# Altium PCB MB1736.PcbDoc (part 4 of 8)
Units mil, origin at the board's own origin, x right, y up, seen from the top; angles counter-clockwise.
Board outline 5905.51 x 3779.53 mil, 6 copper layers (Top Layer, L2_GND, L3_SIG, L4_VCC, L5_GND, Bottom Layer), stack 117.811 mil thick; 481 components, 387 nets, 1904 pads, 1200 vias.
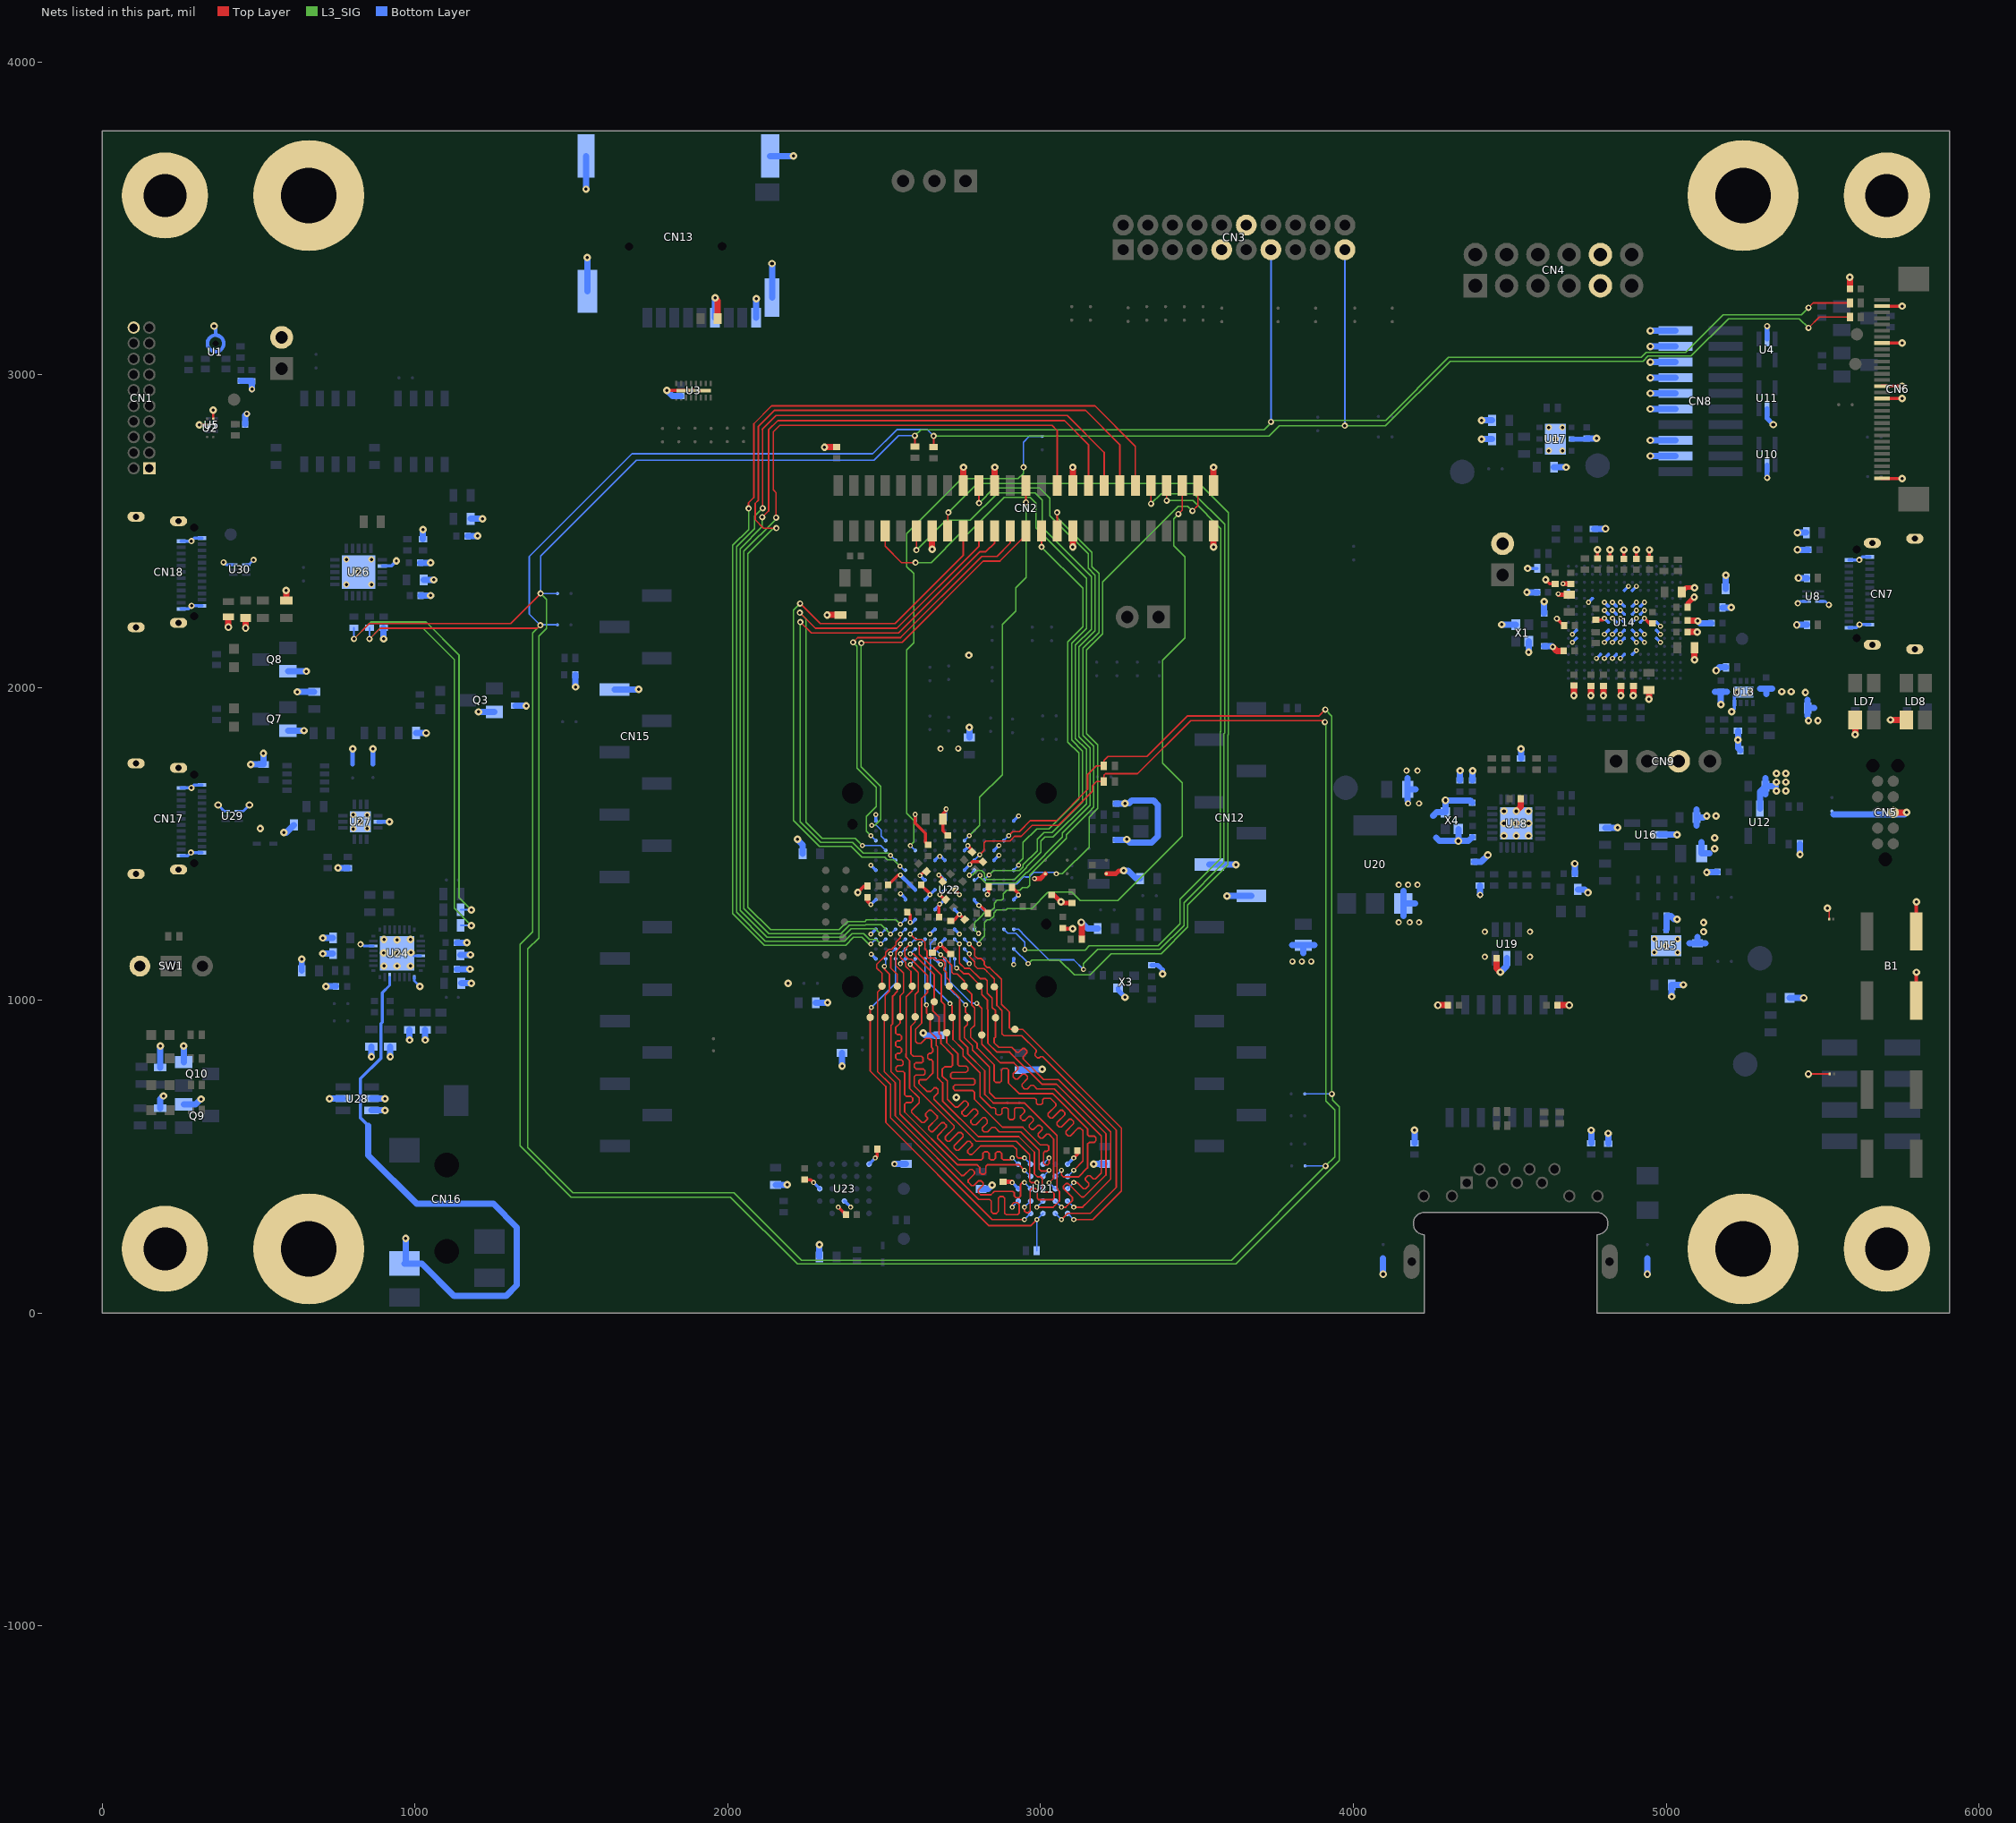
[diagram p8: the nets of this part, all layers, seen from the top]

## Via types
v1: diameter 20, hole 10, Top Layer to Bottom Layer, tented both sides, 518 vias
v2: diameter 16, hole 8, Top Layer to Bottom Layer, tented both sides, 311 vias
v3: diameter 24, hole 10, Top Layer to Bottom Layer, tented both sides, 301 vias
v4: diameter 24, hole 12, Top Layer to Bottom Layer, tented both sides, 61 vias
v5: diameter 23.62, hole 11.81, Top Layer to Bottom Layer, 9 vias

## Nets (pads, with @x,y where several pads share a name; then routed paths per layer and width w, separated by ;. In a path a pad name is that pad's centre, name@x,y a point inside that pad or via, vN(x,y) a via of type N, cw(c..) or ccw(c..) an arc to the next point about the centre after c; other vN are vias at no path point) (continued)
GND: B1.1 B1.2 C1.1 C2.1 C3.1 C13.1 C14.1 C15.2 C17.1 C19.1 C20.1 C21.1 C22.1 C23.1 C24.1 C25.1 C26.1 C27.1 C28.1 C29.1 C30.1 C31.1 C32.1 C33.1 C34.1 C35.1 C36.1 C37.1 C38.1 C39.1 C40.1 C41.1 C42.1 C45.1 C46.1 C47.1 C48.1 C49.1 C50.1 C51.2 C52.2 C53.2 C54.1 C55.2 C56.2 C57.2 C58.2 C59.2 C60.2 C61.2 C62.2 C63.2 C64.2 C65.2 C66.1 C67.2 C68.2 C69.1 C70.1 C71.2 C72.2 C73.2 C75.1 C76.1 C77.2 C78.2 C79.1 C80.1 C81.1 C82.2 C83.1 C84.1 C85.1 C86.1 C87.1 C88.1 C89.1 C90.1 C91.1 C92.1 C93.1 C94.1 C95.1 C96.2 C97.2 C98.1 C99.1 C100.1 C101.1 C102.2 C103.1 C104.1 C105.1 C106.1 C107.2 C108.1 C109.1 C110.1 C111.1 C113.1 C114.1 C115.1 C117.1 C118.1 C119.1 C120.1 C121.1 C122.1 C125.1 C126.2 C127.1 C128.1 C129.1 C130.2 C131.2 C133.2 C134.1 C135.1 C136.1 C139.1 C144.1 C145.2 C146.1 C147.1 C153.2 C156.1 C159.1 C160.1 CN1.1 CN1.20 CN2.1 CN2.2 CN2.19 CN2.20 CN2.30 CN2.34 CN2.37 CN3.5 CN3.16 CN4.5 CN4.11 CN5.3 CN6.1 CN6.14 CN6.16 CN6.23 CN6.29 CN7.A1 CN7.A12 CN7.B1 CN7.B12 CN7.SH1 CN7.SH2 CN7.SH3 CN7.SH4 CN8.3 CN8.5 CN8.9 CN8.11 CN8.13 CN8.15 CN8.17 CN8.19 CN9.3 CN12.6 CN12.7 CN13.6 CN13.9 CN13.11 CN13.12 CN13.13 CN13.14 CN15.7 CN16.3 CN17.A1 CN17.A12 CN17.B1 CN17.B12 CN17.SH1 CN17.SH2 CN17.SH3 CN17.SH4 CN18.A1 CN18.A12 CN18.B1 CN18.B12 CN18.SH1 CN18.SH2 CN18.SH3 CN18.SH4 CN19.2 H1.1 H2.1 H3.1 H4.1 H5.1 H6.1 H7.1 H8.1 JP3.2 LD7.3 LD8.3 LD10.2 Q3.2 Q7.2 Q8.2 Q9.2 Q10.2 R17.1 R66.1 R67.2 R71.2 R72.2 R76.2 R79.2 R84.1 R85.1 R86.2 R87.1 R93.2 R99.2 R101.1 R105.2 R107.1 R113.1 R130.1 R135.1 R145.1 R146.1 R147.2 R152.2 R156.2 R161.2 R162.2 R168.1 R169.1 R177.1 SB28.1 SB39.1 SB62.2 SB63.2 SB69.2 SB70.2 SB71.1 SW1.3 U1.3 U2.2 U2.8 U3.EP U4.2 U5.2 U6.2 U7.2 U8.3 U8.4 U9.2 U10.2 U11.2 U12.2 U13.8 U13.9 U14.D5 U14.D6 U14.D7 U14.D8 U14.D9 U14.F2 U14.F6 U14.F7 U14.F8 U14.F9 U14.F10 U14.F12 U14.G2 U14.G6 U14.G7 U14.G8 U14.G9 U14.G10 U14.G12 U14.H6 U14.H7 U14.H8 U14.H9 U14.H10 U14.H12 U14.J6 U14.J7 U14.J8 U14.J9 U14.J10 U14.K6 U14.K7 U14.K8 U14.K9 U14.K10 U14.L4 U14.M1 U14.M8 U14.M9 U14.N1 U15.2 U15.EP U16.2 U17.2 U17.EP U18.EP U19.2 U20.1 U21.C1 U21.E5 U22.A1 U22.A8 U22.A11 U22.A15 U22.D3 U22.D6 U22.E3 U22.E8 U22.E9 U22.F6 U22.F15 U22.G8 U22.G10 U22.G12 U22.H7 U22.H8 U22.H9 U22.H11 U22.J1 U22.J5 U22.J8 U22.J10 U22.J12 U22.J15 U22.K4 U22.K7 U22.K9 U22.L6 U22.L11 U22.M7 U22.M9 U22.M15 U22.N8 U22.R1 U22.R6 U22.R9 U22.R12 U22.R15 U23.B3 U23.C1 U23.E5 U24.5 U24.9 U24.14 U24.22 U24.33 U26.12 U26.21 U27.2 U27.13 U28.2 U28.3 U28.5 U29.3 U29.4 U30.3 U30.4 U31.2 U32.2 X1.2 X1.4 X3.2 X4.2 X4.4 | length 15911.2
  Top Layer w5: v3(5515.41,1295) 5521.09,1289.31 U6.2@5521.09,1260
  Top Layer w5.5: v4(5455,765) U7.2@5523.39,765
  Top Layer w8: v3(310,2840) 310.68,2840.68 U2.2@334.76,2840.71 ; U2.8@354.45,2860.39 v3(354.47,2888)
  Top Layer w10: v3(1805,2950) U3.EP@1890,2950 ; C14.1@2245.01,427.27 2264.69,427.27 v2(2274.1,417.86) ; v2(2352.84,339.14) 2376.98,314.99 C17.1@2377.3,314.99 ; v3(2415,1345) 2436,1366 C21.1@2446.3,1366 ; C20.1@2446.29,1330 2446.29,1317.39 v2(2457.18,1306.5) ; v2(2470.94,496.6) 2477.74,503.41 C19.1@2477.74,525 ; C22.1@2512.31,1370 2513.24,1370 2544.22,1400.98 v2(2551.67,1400.98) ; C23.1@2574.3,1282 2583.16,1273.11 v2(2583.16,1250) ; v2(2598.9,1595) 2598.9,1566.76 2631.66,1534 2631.66,1506.07 C26.1@2640,1497.73 ; v2(2614.01,1399.19) 2627.28,1412.47 C25.1@2634.54,1412.48 ; C24.1@2617.74,1370 2646.15,1341.58 v2(2646.15,1338) ; C29.1@2654,1152.3 2668.85,1167.14 2679.08,1177.35 v2(2679.08,1179.07) 2703.73,1154.42 2706.65,1154.42 C33.1@2712.65,1148.43 ; v2(2674.71,1400.98) 2686.47,1389.22 C30.1@2686.49,1379.48 ; C28.1@2675.74,1267 2674,1268.73 2674,1302.84 2677,1305.84 v2(2677,1308) ; v2(2677.64,1337.99) 2693.1,1322.52 C31.1@2696.49,1322.53 ; v2(2698,1612) 2698,1608 2687.56,1597.56 2687.56,1543.17 C32.1@2703,1527.73 ; C34.1@2712.65,1253.85 2719.48,1253.85 v2(2740.63,1275) 2757.11,1258.52 C37.1@2757.49,1258.53 ; C35.1@2725.49,1355.48 2740.63,1340.31 v2(2740.63,1338) ; v2(2767,1495) 2780.53,1481.47 C36.1@2780.55,1474.54 ; v2(2772.99,1434.42) 2782.1,1443.52 C38.1@2815.54,1443.53 ; v2(2802.5,1304) 2805.72,1304 2815.86,1293.85 C39.1@2830.74,1279 ; v2(2829.77,1338.76) 2833.72,1342.72 C40.1@2833.73,1363 ; C41.1@2908.73,1362 2928.81,1341.91 v2(2928.81,1337.18) ; v2(3105.79,496.6) 3117.73,508.55 C47.1@3117.74,520 ; v3(4615,2345) 4627.72,2332.27 C51.2@4645,2332.29 ; v1(4650.83,2220.82) C53.2@4673.28,2198.39 ; C58.2@4775.43,2216.91 4797.71,2216.89 v2(4802.63,2221.81) ; C59.2@4780,2412.72 v3(4780,2440.95) ; C61.2@4820,2412.72 v3(4820,2440.95) ; C63.2@4865.1,2412.3 v3(4865.1,2440.53) ; C65.2@4905.05,2412.39 v3(4905.05,2440.61) ; v2(4930.58,2221.81) 4946.74,2205.66 C68.2@4956.19,2205.68 ; C67.2@4946.94,2412.23 v3(4946.94,2440.45) ; C71.2@5068.57,2215.07 C71.2@5070,2215.07 ; C72.2@5068.82,2178.23 C72.2@5070,2178.23 ; CN6.1@5690,2668.82 v3(5755,2668.82) ; CN6.14@5690,2924.73 v3(5755,2924.73) ; CN6.16@5690,2964.09 v3(5755,2964.09) ; CN6.23@5690,3101.89 v3(5755,3101.89) ; CN6.29@5690,3220 v3(5755,3220)
  Top Layer w12: C46.1@3071.01,1229.27 v3@3101.28,1229.27 ; B1.2@5800,1000.02 v3(5800,1090) ; B1.1@5800,1220.49 v3(5800,1315)
  Top Layer w15: C42.1@2880,420.28 2906.54,420.28 v2(2908.95,417.86) ; v2(2980.23,1389.88) 2999.56,1389.88 SB39.1@3015,1405.31 ; C45.1@3035,1337.72 3042.28,1337.72 v3(3065,1315) 3068.34,1311.66 3099.37,1311.66 C48.1@3100,1312.29 ; SB28.1@3210,1405.32 3240.33,1405.32 3250.01,1415 v3(3265,1415) ; v2(4655,2300) 4657.5,2297.5 C54.1@4689.94,2297.5 ; v2(4670,2332.27) C55.2@4695,2332.29 ; C69.1@5050.32,2305.91 5064.41,2320 v3(5090.54,2320) ; C73.2@5068.82,2257.33 5068.81,2268.81 v3(5090,2290)
  Top Layer w20: v4(402.76,2193.85) U31.2@402.76,2226.3 ; v4(457.76,2190.91) C156.1@457.76,2223.35 ; R162.2@587.76,2278.46 v3(587.76,2310.91) ; v3(1958.94,3246.06) 1967.56,3237.43 C13.1@1967.56,3180 ; v3(2308.94,2768.93) C15.2@2347.87,2768.95 ; v3(2317.56,2232.43) R17.1@2360,2232.44 ; v3(2652.87,2442.53) 2652.87,2480 CN2.37@2652.88,2501.22 ; CN2.34@2752.88,2646.31 v3(2752.87,2705) ; CN2.30@2852.88,2646.31 v3(2852.87,2705) ; v3(3102.87,2450) CN2.19@3102.88,2501.22 ; CN2.20@3102.88,2646.31 v3(3102.87,2705) ; v4(3130,1250) 3131.72,1248.28 C75.1@3131.72,1196 ; v3(3552.87,2450) CN2.1@3552.88,2501.22 ; CN2.2@3552.88,2646.31 v3(3552.87,2705) ; v4(4270,985) C92.1@4302.29,985 ; C49.1@4457.29,1135 4457.29,1102.7 v3(4470,1090) ; v5(4520.77,1605.49) 4534.53,1619.25 C50.1@4534.54,1644.84 ; v1(4637.66,2130.27) 4650.29,2117.65 C52.2@4671.95,2117.65 ; C91.1@4652.72,985 v4(4690,985) ; v3(4705.18,1975.17) C56.2@4705.18,2006.34 ; v3(4759.53,1974.5) C57.2@4759.53,2005.48 ; v3(4799.53,1974.45) C60.2@4799.53,2005.44 ; v3(4855.33,1974.57) C62.2@4855.33,2005.55 ; v3(4895.33,1974.6) C64.2@4895.33,2005.59 ; v3(4945,1962.84) C66.1@4945,1992.44 ; C72.2@5070,2178.23 v3(5099.65,2178.23) ; C71.2@5070,2215.07 5099.39,2215.07 v3(5101.46,2213) ; v3(5090.68,2089) C70.1@5090.68,2127.51 ; C76.1@5587.3,3275 v3@5587.3,3312.25 ; v3(5604.47,1850) LD7.3@5604.48,1896.93 ; v3(5716.94,1896.93) LD8.3@5768.49,1896.93 ; CN5.3@5726.3,1601.22 v3(5768.78,1601.22)
  Bottom Layer w8: v3(310,2840) U5.2@338.19,2840 ; v4(370,1625) 389.25,1605.75 U29.3@394.33,1605.74 ; v1(387.76,2400.91) 395.42,2393.25 U30.3@418.33,2393.24 ; U29.4@435.67,1605.74 450.75,1605.75 v4(470,1625) ; U30.4@459.67,2393.24 467.49,2393.25 v1(483,2408.75) ; v1(825,1180) 830,1180 835.59,1174.41 U24.22@866.34,1174.41 ; 895,1025 918.5,1048.5 U24.14@918.5,1075 ; v3(986,1153) 996.09,1142.91 U24.5@1017.91,1142.91 ; U24.9@997.24,1075 997.24,1062.76 v3(1015,1045) ; v2(4670,2332.27) 4682.78,2332.27 U14.N1@4687.5,2336.99 ; v1(5420.72,2270) 5426.97,2276.25 U8.4@5449.33,2276.25 ; U8.3@5490.67,2276.25 5508.75,2276.25 v1(5520,2265)
  Bottom Layer w10: CN17.B12@251.82,1462.88 272.91,1462.89 v1(282.76,1472.74) CN17.A1@312.48,1472.74 ; CN17.B1@251.82,1679.42 v1(284.76,1679.42) 294.61,1689.26 CN17.A12@312.48,1689.26 ; CN18.B12@251.82,2251.88 275.6,2251.89 v1(285.45,2261.74) CN18.A1@318.75,2261.73 ; CN18.B1@251.82,2468.42 v1(284.76,2468.42) 294.61,2478.27 CN18.A12@312.48,2478.27 ; CN17.A1@312.49,1472.73 CN17.A1@318.75,1472.72 ; CN17.A12@312.49,1689.25 CN17.A12@318.75,1689.25 ; CN18.A12@312.49,2478.26 CN18.A12@318.75,2478.26 ; 850,600 825,625 825,750 890,815 890,925 895,930 895,1025 ; U26.12@894.93,2389.41 924.4,2389.4 v3(940,2405) ; v2(2274.1,417.86) U23.C1@2293.78,398.19 ; U23.B3@2372.52,358.81 v2(2392.2,339.14) ; U23.E5@2451.26,476.93 v2(2470.94,496.6) ; v2(2457.18,1212.01) U22.M15@2472.94,1227.77 ; v2(2457.18,1306.5) U22.J15@2472.94,1322.25 ; v2(2457.18,1432.47) 2465.32,1424.33 ; v2(2458.11,1148.09) U22.R15@2472.94,1133.28 ; 2465.34,1424.33 U22.F15@2472.94,1416.75 ; U22.A15@2472.94,1574.23 v2(2472.92,1594) ; v2(2551.67,1117.52) U22.R12@2567.43,1133.28 ; v2(2552.08,1341.58) 2567.42,1326.24 U22.J12@2567.42,1322.25 ; v2(2583.16,1250) 2589.65,1250 U22.L11@2598.93,1259.27 ; U22.A11@2598.9,1574.23 v2(2598.9,1595) ; v2(2614.01,1399.19) 2627.96,1385.25 U22.G10@2630.42,1385.25 ; U22.J10@2630.4,1322.25 v2(2646.15,1338) U22.H9@2661.92,1353.76 ; v2(2646.15,1212.01) U22.M9@2661.92,1227.77 ; U22.R9@2661.9,1133.25 v2(2680.08,1115.08) ; U22.K9@2661.9,1290.75 2677,1305.84 v2(2677,1308) 2679.15,1308 U22.J8@2693.39,1322.24 ; U22.E9@2661.89,1448.23 2674.36,1460.69 v2(2677.5,1460.69) 2680.92,1460.69 2687.81,1453.81 U22.E8@2693.4,1448.24 ; v2(2674.71,1400.98) 2677,1400.98 2679.98,1398 2680.63,1398 2686.31,1392.32 U22.G8@2693.4,1385.25 ; v2(2679.08,1179.07) 2679.08,1181.94 U22.N8@2693.42,1196.27 ; U22.J8@2693.38,1322.25 v2(2677.64,1337.99) U22.H8@2693.42,1353.76 ; U22.A8@2693.39,1574.2 2695.5,1576.32 2695.5,1605.5 2698,1608 v2(2698,1612) ; U22.M7@2724.89,1227.75 v2(2740.63,1212.01) ; U22.K7@2724.89,1290.75 v2(2740.63,1275) U22.L6@2756.38,1259.25 ; U22.H7@2724.9,1353.75 2732.31,1346.34 ; 2732.31,1346.32 v2(2740.63,1338) ; U22.F6@2756.38,1416.73 2772.12,1432.47 2772.12,1433.55 v2(2772.99,1434.42) ; U22.D6@2756.38,1479.72 2767,1490.34 v2(2767,1495) ; U22.R6@2756.39,1133.27 2762.82,1126.84 ; 2762.82,1126.83 v2(2772.12,1117.52) ; U22.J5@2787.89,1322.25 2787.89,1319.1 2802.5,1304.5 v2(2802.5,1304) 2803,1304 2816.25,1290.75 U22.K4@2819.37,1290.75 ; U22.E3@2850.9,1448.24 v2(2866.61,1463.97) ; U22.D3@2850.9,1479.74 v2(2866.61,1495.45) ; v2(2908.95,417.86) U21.C1@2928.63,398.19 ; U22.R1@2913.89,1133.28 2913.86,1115.27 v2(2914,1115.14) ; U22.J1@2913.87,1322.25 v2(2928.81,1337.18) ; U22.A1@2913.89,1574.23 v2(2929.6,1589.94) ; U21.E5@3086.11,476.93 v2(3105.79,496.6) ; v3(4557.4,2381.7) R93.2@4587.6,2381.7 ; v2(4655,2300) 4676.1,2300 U14.M1@4687.5,2311.4 ; v2(4700.27,2145.03) U14.F2@4713.09,2157.85 ; v2(4700.27,2170.62) U14.G2@4713.09,2183.44 ; v2(4751.46,2272.98) U14.L4@4764.27,2285.81 ; v2(4777.04,2093.85) U14.D5@4789.86,2106.67 ; v2(4802.63,2093.85) U14.D6@4815.45,2106.67 ; v2(4802.63,2145.03) U14.F6@4815.45,2157.85 ; v2(4802.63,2170.62) U14.G6@4815.45,2183.44 ; v2(4802.63,2221.81) U14.H6@4815.45,2209.03 ; v2(4802.63,2247.4) U14.J6@4815.45,2234.63 ; v2(4802.63,2273) U14.K6@4815.45,2260.22 ; v2(4828.22,2093.85) U14.D7@4841.04,2106.67 ; v2(4828.22,2145.03) U14.F7@4841.04,2157.85 ; v2(4828.22,2170.62) U14.G7@4841.04,2183.44 ; v2(4828.22,2221.81) U14.H7@4841.04,2209.03 ; v2(4828.22,2247.4) U14.J7@4841.04,2234.63 ; v2(4828.22,2273) U14.K7@4841.04,2260.22 ; v2(4853.81,2093.85) U14.D8@4866.64,2106.67 ; v2(4853.81,2145.03) U14.F8@4866.64,2157.85 ; v2(4853.81,2170.62) U14.G8@4866.64,2183.44 ; v2(4853.81,2221.81) U14.H8@4866.64,2209.03 ; v2(4853.81,2247.4) U14.J8@4866.64,2234.63 ; v2(4853.81,2273) U14.K8@4866.64,2260.22 ; U14.M8@4866.64,2311.4 v2(4879.41,2324.17) ; U14.D9@4892.23,2106.67 v2(4905.03,2119.43) ; U14.F9@4892.2,2157.83 v2(4904.99,2145.03) ; U14.G9@4892.2,2183.42 v2(4904.99,2170.62) ; U14.H9@4892.2,2209.01 v2(4904.99,2221.81) ; U14.J9@4892.23,2234.63 v2(4904.99,2247.4) ; U14.K9@4892.23,2260.22 v2(4904.99,2273) ; U14.M9@4892.23,2311.4 v2(4905,2324.17) ; U14.F10@4917.79,2157.83 v2(4930.58,2145.03) ; U14.G10@4917.79,2183.42 v2(4930.58,2170.62) ; U14.H10@4917.79,2209.01 v2(4930.58,2221.81) ; U14.J10@4917.79,2234.6 v2(4930.58,2247.4) ; U14.K10@4917.82,2260.22 v2(4930.58,2273) ; U14.G12@4969,2183.44 4975.1,2177.3 v2(4981.76,2170.62) ; U14.H12@4969,2209.03 v2(4981.76,2196.22) ; U14.F12@4969,2157.85 v2(4981.76,2145.03) ; v3(5209.5,1923.5) 5218.52,1932.51 5218.52,1977.19 v1(5227.7,1986.4) ; CN7.A12@5584.02,2191.73 CN7.A12@5590.28,2191.73 ; CN7.A1@5584.03,2408.25 v1(5617.32,2408.25) 5627.17,2418.1 CN7.B12@5650.93,2418.1 ; CN7.A12@5590.29,2191.72 5608.16,2191.72 v1(5618.01,2201.57) CN7.B1@5650.93,2201.56
  Bottom Layer w12: v4(357.24,3156.09) 361.99,3151.34 U1.3@361.99,3126.82 ; U27.2@881.13,1571.24 v3(918.22,1571.22) ; v2(2551.67,1400.98) 2567.39,1385.25 U22.H11@2598.92,1353.76
  Bottom Layer w15: SB63.2@800,1754.86 v3(800,1805) ; SB62.2@865,1756.24 v3(865,1805) ; X3.2@3247.52,1039.75 3247.52,1032.48 v3(3270,1010) ; C107.2@3355,1112.72 3375,1112.72 3390,1097.72 v3(3390,1085.5) ; U17.2@4697.23,2794.8 4743.73,2794.77 C90.1@4746.02,2797.08 ; v1(5322.76,2670.91) U10.2@5322.76,2712.44 ; U11.2@5322.76,2892.44 5322.76,2860.91 v4(5342.76,2840.91) ; U4.2@5322.76,3114.36 v1(5322.76,3155.9)
  Bottom Layer w20: R168.1@185,655.72 185,685 v3(195,695) ; R169.1@185,785.72 v3(185,855) ; Q9.2@260.02,668.16 298.16,668.16 v3(315,685) ; Q10.2@260,802.97 v3(260,855) ; C3.1@442.55,2980.64 477.65,2980.64 C2.1@478,2980.28 v1(478,2954) ; C1.1@456.72,2842 456.72,2870.72 v1(462,2876) ; v3(474.61,1754.6) U32.2@515,1754.62 v3(515,1790) ; v3(580,1537) 588.22,1537 C153.2@612.44,1561.22 ; Q7.2@593.32,1862.6 v3(645,1862.59) ; Q8.2@593.32,2052.6 v3(652.4,2052.59) ; v3(623.14,1986.85) R161.2@677.46,1986.85 ; C133.2@637.44,1095 v3(637.44,1132.56) ; v3(705,1150) C134.1@737.44,1150 ; v3(705,1200) C135.1@737.44,1200 ; v3(714.84,1045) C129.1@747.28,1045 ; v3(726.18,686.22) U28.5@769.71,686.24 ; v3@753.52,1423.51 R156.2@785,1423.52 ; 850,600 850,505 1005,350 1250,350 1325,275 1325,90 1290,55 1125,55 1021.31,158.69 CN16.3@965.77,158.69 970,162.94 v3(970,240) ; v3(860,820) R145.1@860,852.44 ; U28.3@860.26,648.83 v3(903.78,648.82) ; U28.2@860.26,686.24 v3(903.78,686.22) ; v3(899.12,2155.88) R152.2@899.12,2192.01 ; v3(920,820) R146.1@920,852.44 ; v3(982.13,873.94) C131.2@982.13,906.38 ; R113.1@1002.56,1855 v4(1035,1855) ; C147.1@1015.46,2399.6 v3(1049.61,2399.6) ; C146.1@1017.74,2294.6 v3(1049.61,2294.6) ; R147.2@1025,2474.62 v3(1025,2505) ; C145.2@1027.56,2344.6 v3(1059.61,2344.6) ; v3(1032.13,873.94) C130.2@1032.13,906.38 ; C144.1@1132.72,1100 v3(1175,1100) ; C128.1@1132.72,1185 v3(1165,1185) ; C139.1@1144.69,1145.79 v3(1177.13,1145.79) ; C127.1@1147.56,1055 v3(1180,1055) ; C136.1@1167.74,2485 v3(1200,2485) ; R135.1@1177.56,2540 v3(1215,2540) ; v3(1202.4,1922.59) Q3.2@1253.33,1922.61 ; R130.1@1320,1942.3 1334.99,1942.28 ; 1335,1942.27 v3(1355,1942.27) ; v3@1512.46,2002.58 C126.2@1512.46,2041.22 ; v3(1546.53,3593.47) CN13.12@1546.54,3699.94 ; CN13.13@1550.48,3266.87 v3(1550.47,3375) ; CN15.7@1637.41,1994.25 1658.99,1994.25 v3(1715,1994.25) ; v3(1805,2950) 1822.72,2932.27 C125.1@1850,2932.3 ; CN13.6@1958.94,3182.22 v3(1958.94,3246.06) ; CN13.9@2090.83,3182.22 v3(2090.83,3244.17) ; CN13.11@2135.12,3699.94 v3(2209.92,3699.92) ; CN13.14@2141.03,3247.18 v4(2141.03,3356.02) ; C122.1@2152.52,410.65 v3(2190,410.62) ; v3(2222,1515) 2239.32,1497.68 C121.1@2239.32,1469 ; C114.1@2281.12,993 v3(2319,993) ; C119.1@2292.44,179.99 v3(2292.44,219.99) ; v3(2365,790.27) C118.1@2365,832.45 ; v1(2532.56,477.43) C117.1@2569.99,477.43 ; v3(2624,896) 2631.12,888.88 C115.1@2675,888.88 ; C120.1@2772,1841.12 v3(2772,1873) ; C113.1@2810,397.44 2832.45,397.44 v3(2845,409.99) ; C111.1@2935,777.45 2967.52,777.43 2970.08,780 v3(3005,780) ; v4(3130,1250) 3150,1230 C105.1@3182.44,1230 ; v3@3170.01,477.44 C110.1@3205,477.44 ; C108.1@3240.87,1513.84 3273.83,1513.83 v3(3275,1515) 3285,1505 3355,1505 3375,1525 3375,1625 3360,1640 3292.26,1640 3282.26,1630 v3(3270,1630) 3269.22,1629.22 3240.92,1629.22 C109.1@3240.87,1629.27 ; v3(3265,1415) 3280,1415 3305,1390 C106.1@3317.44,1390 ; CN12.6@3539,1434.25 3564,1434.25 v3(3625,1434.25) ; v3(3595.75,1334.25) 3658.97,1334.25 CN12.7@3673.98,1334.25 ; 3804.42,1176.55 C104.1@3840,1176.55 ; 3840,1150.81 C104.1@3840,1176.55 ; 3875.58,1176.55 C104.1@3840,1176.55 ; v4(4095,124.99) SB70.2@4095,176.37 ; 4159.75,1269.61 U20.1@4159.76,1310.11 ; 4159.75,1350.61 U20.1@4159.76,1310.11 ; v1@4173.48,1639.42 C103.1@4173.48,1675 ; 4173.48,1710.58 C103.1@4173.48,1675 ; R107.1@4195.76,543.44 v3(4195.76,585.75) ; 4197.3,1310.11 U20.1@4159.76,1310.11 ; 4199.21,1675 C103.1@4173.48,1675 ; 4255,1590 4266.57,1601.57 X4.2@4294.33,1601.56 v4(4294.33,1640) 4372.72,1640 C160.1@4380,1632.72 ; 4265,1520 4275,1510 v4(4335.67,1510) ; X4.4@4335.67,1548.42 v4(4335.67,1510) ; C101.1@4340.75,1703.83 v3(4340.75,1735) ; C159.1@4380,1522.27 4367.72,1510 v4(4335.67,1510) ; C99.1@4380.75,1703.83 v3(4380.75,1734.75) ; C98.1@4385.75,1443.4 4408.4,1443.4 v4(4430,1465) ; v1(4405,1337.59) R105.2@4405,1367.3 ; v3(4409.88,2854.77) C97.2@4443.48,2854.77 ; v3(4410,2794.77) R101.1@4443.48,2794.77 ; v3(4470,1090) 4490.76,1110.75 4490.76,1118 U19.2@4490.78,1135.45 ; v3(4474.76,2201.58) X1.2@4519.33,2201.57 ; R99.2@4535.75,1773.83 v3(4535.75,1805) ; v3(4555,2305) C94.1@4587.3,2305 ; v3(4560.67,2113.91) X1.4@4560.67,2148.43 ; C95.1@4610,2132.29 4635.66,2132.27 v1(4637.66,2130.27) ; C96.2@4610,2237.72 v3(4610,2275) ; C93.1@4641.54,2705.22 4679.78,2705.22 v3(4680,2705) ; C100.1@4707.72,1405 v4(4707.72,1437.72) ; C102.2@4717.56,1355 4740,1355 v4(4750,1345) ; C90.1@4746.03,2797.06 v3(4777.54,2797.06) ; R87.1@4760.76,543.44 v3(4760.76,585) ; R86.2@4769.18,2508.25 v4(4805.95,2508.25) ; R84.1@4805,1552.56 v3(4845,1552.56) ; R85.1@4815,542.73 v3(4815,575) ; v4(4940,124.99) SB69.2@4940,176.37 ; v4(4949.67,2741) CN8.3@5029.89,2741 ; v4(4949.67,2791) CN8.5@5029.89,2791 ; v4(4949.67,2891) CN8.9@5029.89,2891 ; v4(4949.67,2941) CN8.11@5029.89,2941 ; v4(4949.67,2991) CN8.13@5029.89,2991 ; v4(4949.67,3041) CN8.15@5029.89,3041 ; v4(4949.67,3091) CN8.17@5029.89,3091 ; v4(4949.67,3141) CN8.19@5029.89,3141 ; U16.2@4978.3,1530 v3(5035,1530) ; U15.2@5000,1226.17 5000.72,1226.9 C89.1@5000.75,1270 ; C89.1@5000.75,1270 5015,1270 5025,1260 v3(5035,1260) ; v3(5017.56,1012.56) C88.1@5017.56,1050 v3(5055,1050) ; 5074.46,1182.58 C86.1@5100,1182.57 ; 5097.56,1559.45 C87.1@5097.56,1585 ; 5097.56,1610.53 C87.1@5097.56,1585 ; 5100,1203.19 C86.1@5100,1182.57 ; v3(5101.46,2213) 5108.24,2206.22 C83.1@5145.18,2206.22 ; 5113.46,1505.58 C85.1@5113.46,1470 5139.2,1470 ; 5118.18,1585 C87.1@5097.56,1585 ; 5125.54,1182.58 C86.1@5100,1182.57 ; v3(5130,1410) 5164.15,1410 C81.1@5165.05,1410.9 ; 5155.95,1987.27 C84.1@5175,1987.29 ; 5155.95,1987.28 C84.1@5175,1987.29 5194.05,1987.28 ; v4(5160,2055) 5170,2065 R177.1@5192.28,2065 ; v3(5175,1946.55) C84.1@5175,1987.29 ; R79.2@5180.61,2256.22 v3(5208.29,2256.22) ; C82.2@5190.44,2316.22 v3(5190.44,2359.56) ; 5194.05,1987.27 C84.1@5175,1987.29 ; R76.2@5230,1862.29 v3(5230,1833) 5230,1807.28 R67.2@5237.3,1800 ; U12.2@5300,1613.31 5300,1667.43 C80.1@5317.56,1685 ; 5300.95,1997.27 C78.2@5320,1997.28 ; 5317.56,1659.45 C80.1@5317.56,1685 ; 5317.56,1710.53 C80.1@5317.56,1685 ; 5320,1979.22 C78.2@5320,1997.28 ; 5339.05,1997.27 C78.2@5320,1997.28 ; 5350,1685 C80.1@5317.56,1685 ; LD10.2@5394.51,1008 v4(5440,1008) ; v4(5417.76,2200.91) R71.2@5450.05,2200.9 ; v4(5420,2440.9) C77.2@5455.06,2440.9 ; v4(5420,2495.9) U9.2@5448.17,2495.9 ; v4(5423,2350.9) R72.2@5450.05,2350.9 ; v3(5427.72,1467.27) R66.1@5427.73,1500 ; 5452.56,1909.45 C79.1@5452.56,1935 ; 5452.56,1960.53 C79.1@5452.56,1935 ; 5473.18,1935 C79.1@5452.56,1935 ; 5535,1595 5762.57,1595 v3(5768.78,1601.22)
  other v1: 3805,1125 3835,1125 3865,1125 4420,1140 4565,1140 5037,1153 4962.7,1153.8 5000,1175 5037,1196 4962.7,1196.9 4420,1220 4565,1220 4145,1250 4180,1250 4210,1250 4145,1370 4175,1370 4205,1370 802,1549 847,1550 825,1571.22 847,1593 802,1594 4175,1630 4210,1630 4170,1735 4205,1735 2679.76,1804.91 2736.76,1805.91 5268.5,1986.19 780,2330 860,2330 819.12,2369.7 780,2410 860,2410 4624.7,2757.5 4668.6,2757.9 4646.02,2794.77 4624.7,2832.19 4668.2,2831.69
  other v3: 3170,477.43 2730,690 2193,1055 900,1110 942,1110 985,1110 942.13,1150.79 899,1152 942,1194 900,1195 985,1195 5120,1220 3102,1230 5120,1250 753.5,1423.5 5155,1485 5155,1520 505,1550 5130,1590 5159,1590 5353,1670 5383,1670 5353,1698 5383,1698 5353,1726 5383,1726 5455,1895 5485,1895 5445,1985 5370,1987 5400,1987 1512.44,2002.56 2770.87,2104.12 5587.28,3312.27
  other v5: 4481.4,1526.74 4520.77,1526.74 4560.15,1526.74 4481.4,1566.11 4520.77,1566.11 4560.15,1566.11 4481.4,1605.49 4560.15,1605.49
HEXASPI_CLK: TP13.1 U21.B2 U22.R10 | length 1275.2
  Top Layer w5: v2(2635,985.75) 2635,959.67 TP13.1@2646.76,947.91 2646.76,899.42 2666.28,879.91 2666.28,856.27 2670,852.56 2670,753 2686.53,736.48 2686.53,678.6 2800.14,565 2930,565 2980,515 2980,445.99 2990,435.99 3001,435.99 3005,431.99 3005,392.57 3010,387.57 3038,387.57 3043,382.57 3043,368.01 3037.99,362.99 2994,362.99 2989,367.99 2989,393.99 2984,398.99 2971.67,398.99 2966.67,393.99 2966.67,326.99 2961.67,321.99 2953.32,321.99 2948.32,326.99 v2(2948.32,339.14)
  Bottom Layer w5: U22.R10@2630.42,1133.28 2630.41,994.59 2635,990 v2(2635,985.75) ; v2(2948.32,339.14) U21.B2@2968,358.81
HEXASPI_DQS0: TP14.1 U21.C3 U22.N11 | length 1275.4
  Top Layer w5: v2(2583.16,1180.51) 2566.17,1163.52 2566.17,1143.83 2577.5,1132.5 2587.5,1132.5 2594.91,1125.09 2594.91,1123.82 2637.76,1080.97 TP14.1@2637.76,1045.91 2637.76,1025.03 2619.76,1007.03 2619.76,992.44 2619.5,992.18 2619.5,927.66 2600,908.16 2600,869 2606,863 2617.61,863 2633.3,878.68 2646.28,878.68 2651.28,873.68 2651.28,850.06 2655,846.34 2655,836.34 2650,831.34 2644,831.34 2639,826.34 2639,816.34 2644,811.34 2650,811.34 2655,806.34 2655,767.58 2634.2,746.77 2613.5,746.77 2611,744.27 2611,735 2636.88,709.11 2647.96,709.11 2659.38,720.53 2666.46,720.53 2671.53,715.47 2671.53,704.39 2659.07,691.92 2659.07,684.84 2793.92,550 2922,550 2965,507 2965,422.86 2970,417.86 v2(2987.69,417.86)
  Bottom Layer w5: v2(2583.16,1180.51) U22.N11@2598.93,1196.27 ; v2(2987.69,417.86) U21.C3@3007.37,398.19
HEXASPI_DQS1: TP23.1 U21.B3 U22.M11 | length 1277.9
  Top Layer w5: v2(2583.16,1212.01) 2600.18,1195 2608.63,1195 ; 2608.65,1195.01 2620.67,1195.01 2630,1185.68 2630,1164.99 2636.47,1158.51 2636.47,1139.55 2640.27,1135.75 2659.24,1135.75 2665.41,1129.58 2686.09,1129.58 2694.58,1121.09 2694.58,1109.07 2690.58,1105.07 2690.58,1097.91 2698.76,1089.73 2698.76,1073.95 2707.76,1064.95 TP23.1@2707.76,1045.91 2707.76,1041.91 2741.28,1008.39 2741.28,874.93 2767.1,849.11 2767.1,829.17 2821.1,775.17 2821.1,699.67 2848.29,672.49 2947.51,672.49 3051.92,568.08 3051.92,398.07 3060,389.99 3060,358.99 3040.14,339.14 v2(2987.69,339.14)
  Bottom Layer w5: v2(2583.16,1212.01) U22.M11@2598.93,1227.77 ; v2(2987.69,339.14) U21.B3@3007.37,358.81
HEXASPI_IO0: TP15.1 U21.D3 U22.P11 | length 1276.2
  Top Layer w5: v2(2583.16,1149.01) 2593.13,1149.01 2659.76,1082.39 TP15.1@2659.76,995.91 2654.99,991.13 2654.99,968.01 2675,948 2675,893.67 2681.28,887.39 2681.28,862.5 2718,825.77 2718,792 2714,788 2692.99,788 2685,780 2685,759.23 2701.53,742.69 2701.53,684.83 2727.33,659.02 2734.41,659.02 2754.15,678.76 2761.23,678.76 2768.3,671.69 2768.3,664.61 2748.56,644.88 2748.56,637.8 2755.63,630.73 2762.71,630.73 2784.95,652.97 2792.03,652.97 2799.1,645.9 2799.1,638.82 2776.86,616.58 2776.86,609.5 2783.36,603 2793,603 2815.5,625.5 2821.5,625.5 2828.96,618.03 2828.96,607.95 2813.54,592.53 2813.54,585.45 2819,580 2830,580 2844,594 2854,594 2868,580 2936.22,580 2995,521.22 2995,461 3001,455 3024.81,455 v2(3027.05,457.24)
  Bottom Layer w5: v2(2583.16,1149.01) U22.P11@2598.93,1164.78 ; U21.D3@3007.37,437.56 v2(3027.05,457.24)
HEXASPI_IO1: TP16.1 U21.D2 U22.N12 | length 1267.2
  Top Layer w5: v2(2551.67,1180.51) 2551.67,1171.67 2540,1160 2540,1157.85 2537.17,1155.02 2537.17,1111.51 2561.28,1087.41 2561.28,1025.42 2550.76,1014.91 TP16.1@2550.76,947.91 2550.76,927.59 2536.28,913.1 2536.28,896.03 2541.28,891.03 2550,891.03 2555,886.03 2555,876.03 2550,871.03 2541.28,871.03 2536.28,866.03 2536.28,856.03 2541.28,851.03 2550,851.03 2555,846.03 2555,836.03 2550,831.03 2541.28,831.03 2536.28,826.03 2536.28,816.72 2543,810 2555,810 2560,805 2560,796 2556,792 2543,792 2537,786 2537,778 2542,773 2560,773 2565,768 2565,698.77 2570,693.77 2585,693.77 2591,687.77 2591,678.77 2586,673.77 2570,673.77 2565,668.77 2565,643.66 2733.66,475 2796.31,475 2805.11,466.19 2805.11,449.99 2810.11,444.99 2820.11,444.99 2825.11,449.99 2825.11,470 2830.11,475 2930.56,475 v2(2948.32,457.24)
  Bottom Layer w5: v2(2551.67,1180.51) U22.N12@2567.43,1196.27 ; v2(2948.32,457.24) U21.D2@2968,437.56
HEXASPI_IO2: TP17.1 U21.C4 U22.N9 | length 1273.5
  Top Layer w5: v2(2710,990) 2716.76,983.24 TP17.1@2716.76,945.91 2720,942.67 2720,904.74 2719.76,904.5 2719.76,875.24 2752.1,842.9 2752.1,822.95 2806.1,768.95 2806.1,693.45 2842.07,657.49 2851.13,657.49 2856.13,652.49 2856.13,639 2861.13,634 2871.13,634 2876.13,639 2876.13,652.49 2881.13,657.49 2891.13,657.49 2896.13,652.49 2896.13,625 2902.13,619 2911.13,619 2916.13,624 2916.13,652.49 2921.13,657.49 2941.29,657.49 2948.38,650.4 2948.38,643.32 2935.57,630.5 2935.57,623.42 2942.64,616.35 2949.72,616.35 2962.53,629.17 2969.61,629.17 2976.68,622.09 2976.68,615.01 2963.87,602.2 2963.87,595.12 2970.94,588.06 2978.02,588.06 2990.83,600.86 2997.91,600.86 3004.98,593.8 3004.98,586.72 2992.17,573.91 2992.17,566.83 2999.24,559.75 3006.32,559.75 3019.13,572.57 3026.21,572.57 3041.56,557.22 3041.55,552.34 3041.55,431.95 v2(3027.05,417.45)
  Bottom Layer w5: U22.N9@2661.92,1196.27 2647.57,1181.93 2647.57,1052.42 v2(2710,990) ; v2(3027.05,417.45) 3027.47,417.45 U21.C4@3046.74,398.19
HEXASPI_IO3: TP18.1 U21.D4 U22.P9 | length 1270.9
  Top Layer w5: v2(2680.33,1146.32) 2688.07,1138.58 2689.82,1138.58 2715.76,1112.64 2715.76,1090.24 2721,1085 2732.72,1085 2755.76,1061.95 TP18.1@2755.76,1045.91 2755.76,1042.91 2780,1018.67 2780,985 2788.76,976.24 2788.76,920.91 2776.03,908.17 2776.03,882.62 2797.1,861.56 2797.1,848.11 2851.11,794.1 2851.11,742.89 2856,738 2870,738 2875,743 2875,778 2880,783 2892,783 2897,778 2897,736 2930.5,702.5 3037.62,702.5 3150,590.11 3150,571.03 3155,566.03 3172,566.03 3177,561.03 3177,552.03 3171,546.03 3155,546.03 3150,541.03 3150,464.99 3121.01,435.99 3073,435.99 3066.42,442.57 v2(3066.42,457.24)
  Bottom Layer w5: U22.P9@2661.9,1164.75 v2(2680.33,1146.32) ; U21.D4@3046.74,437.56 v2(3066.42,457.24)
HEXASPI_IO4: TP19.1 U21.D5 U22.R8 | length 1275.6
  Top Layer w5: v2(2760,985.75) 2760,962.72 2765.76,956.95 TP19.1@2765.76,944.91 2765.76,923.03 2756.28,913.56 2756.28,881.16 2782.1,855.34 2782.1,841.9 2836.1,787.9 2836.1,705.9 2854.5,687.5 2918.5,687.5 2981.25,687.49 2986.25,682.49 2986.25,672 2991.25,667 3001.25,667 3006.25,672 3006.25,682.49 3011.25,687.49 3031.41,687.49 3048.53,670.36 3048.53,663.28 3023.66,638.42 3023.66,631.34 3030.73,624.26 3037.81,624.26 3062.68,649.14 3069.76,649.14 3077.12,641.77 3077.12,634.69 3052.25,609.83 3052.25,602.75 3059.32,595.67 3066.4,595.67 3091.27,620.55 3098.35,620.55 3105.42,613.48 3105.42,606.4 3080.55,581.52 3080.55,574.44 3087.62,567.38 3094.7,567.38 3119.57,592.25 3126.65,592.25 3135,583.9 3135,486.44 v2(3105.79,457.24)
  Bottom Layer w5: U22.R8@2693.4,1133.27 2695,1131.67 2695,1050.75 v2(2760,985.75) ; U21.D5@3086.11,437.56 v2(3105.79,457.24)
HEXASPI_IO5: TP20.1 U21.E3 U22.N10 | length 1276.9
  Top Layer w5: v2(2614.66,1180.51) 2611.6,1177.45 2611.6,1148.4 2646.95,1113.05 2650.32,1113.05 2682.76,1080.6 2682.76,996.24 2692.76,986.24 2692.76,903.91 TP20.1@2699.76,896.91 2699.76,865.24 2735.15,829.84 2735.15,795.34 2740.15,790.34 2762.2,790.34 2767.2,785.34 2767.2,776.34 2761.2,770.34 2717.15,770.34 2712.15,765.34 2712.15,755.34 2717.15,750.34 2785,750.34 2790,745.34 2790,735.34 2785,730.34 2726.15,730.34 2721,725.18 2721,717 2726,712 2783,712 2788,707 2788,685 2878,595 2942.44,595 2998.72,538.72 3021.28,538.72 3026,534 3026,523 3021,518 3014,518 3009,513 3009,479.99 3014.97,474.01 3022.05,474.01 3027.05,479.01 v2(3027.05,496.6)
  Bottom Layer w5: v2(2614.66,1180.51) U22.N10@2630.42,1196.27 ; U21.E3@3007.37,476.93 v2(3027.05,496.6)
HEXASPI_IO6: TP21.1 U21.E2 U22.R11 | length 1268.9
  Top Layer w5: v2(2583.22,1115) 2605.68,1092.53 2605.68,1091.83 2609.07,1088.43 2609.07,1029.22 2598.76,1018.91 TP21.1@2598.76,947.91 2598.76,931.03 2585,917.27 2585,829 2592.5,821.5 2619,821.5 2624,816.5 2624,805.08 2619.92,801 2601,801 2596,796 2596,787 2602,781 2625.08,781 2630.08,776 2630.08,765.85 2626,761.77 2601,761.77 2596,756.77 2596,726.69 2723.42,599.27 2723.42,592.22 2695.08,563.89 2695.08,556.83 2702.17,549.74 2709.23,549.74 2737.57,578.07 2744.63,578.07 2751.72,570.98 2751.72,563.92 2723.38,535.59 2723.38,528.52 2730.47,521.43 2737.53,521.43 2765.87,549.76 2772.93,549.76 2780.79,541.91 2780.79,534.83 2766.82,520.85 2766.82,513.77 2773.04,507.56 2780.12,507.56 2807.56,535 2912.25,535 2923.45,523.8 2923.45,501.35 2928.2,496.6 v2(2948.32,496.6)
  Bottom Layer w5: v2(2583.22,1115) 2598.91,1130.68 U22.R11@2598.93,1133.28 ; v2(2948.32,496.6) U21.E2@2968,476.93
HEXASPI_IO7: TP22.1 U21.E1 U22.P12 | length 1278.7
  Top Layer w5: v2(2551.67,1149.01) 2551.67,1138.34 2568.72,1121.28 2568.72,1108.99 2585,1092.7 2585,1050.67 TP22.1@2589.76,1045.91 2589.76,1031.92 2570.07,1012.23 2570.07,923.57 2570,923.5 2570,829.82 2569.76,829.58 2569.76,819.01 2581,807.77 2581,719 2611.5,688.5 2611.5,672.5 2587.54,648.53 2587.54,642.34 2613.12,616.75 ; 2613.14,616.75 2620.21,609.68 2627.29,609.68 2637.8,620.19 2637.8,625.19 2632.04,630.95 2632.04,638.03 2643.46,649.45 2650.54,649.45 2669.44,630.56 2669.44,623.48 2641.52,595.56 2641.52,588.35 2649.47,580.41 2654.67,580.41 2683.59,609.33 2690.67,609.33 2697.9,602.09 2697.9,595.01 2669.92,567.03 2669.92,559.95 2739.28,490.59 2810.22,490.59 2815.22,495.59 2815.22,511.43 2820.22,516.43 2830.22,516.43 2835.22,511.43 2835.22,495.59 2840.22,490.59 2850.22,490.59 2855.22,495.59 2855.22,511.43 2860.22,516.43 2870.22,516.43 2875.22,511.43 2875.22,495.59 2880.22,490.59 2902.94,490.59 v2(2908.95,496.6)
  Bottom Layer w5: v2(2551.67,1149.01) U22.P12@2567.43,1164.78 ; v2(2908.95,496.6) U21.E1@2928.63,476.93
HEXASPI_IO8: TP24.1 U21.C2 U22.P13 | length 1272.3
  Top Layer w5: v2(2520.57,1149.42) 2520.57,1104.42 2541.76,1083.24 TP24.1@2541.76,1045.91 2541.76,1028.9 2526.76,1013.9 2526.76,925.39 2521.28,919.91 2521.28,772.36 2550,743.65 2550,637.43 2746.76,440.68 2754.83,440.68 2774.04,459.91 2781.1,459.91 2788.19,452.81 2788.19,445.76 2768.48,426.02 2768.48,418.95 2779.16,408.27 2786.24,408.27 2800.94,422.98 2810.02,422.98 2816.09,416.9 2816.09,409.82 2800.39,394.12 2800.39,387.05 2808.44,378.99 2841.31,378.99 2852.31,389.99 2910.81,389.99 2915.81,384.99 2915.81,374.99 2920.81,369.99 2930.81,369.99 2935.81,374.99 2935.81,412.86 2940.81,417.86 v2(2948.32,417.86)
  Bottom Layer w5: v2(2520.57,1149.42) U22.P13@2535.94,1164.78 ; v2(2948.32,417.86) U21.C2@2968,398.19
HEXASPI_IO9: TP25.1 U21.B1 U22.R14 | length 1270.3
  Top Layer w5: v2(2500.45,1109.49) 2500.45,1100.76 2516.28,1084.93 2516.28,1029.42 2502.76,1015.9 TP25.1@2502.76,945.91 2500,943.15 2500,772.42 2535,737.42 2535,631.22 2802.22,363.99 2837,363.99 2842,358.99 2842,324.99 2847.96,319.03 2858.04,319.03 2865,325.99 2865,367.99 2870,372.99 2880,372.99 2885,367.99 2885,319.99 2890,314.99 2926,314.99 2931,319.99 2931,348.11 2925,354.11 2914.12,354.11 2908.95,348.94 v2(2908.95,339.14)
  Bottom Layer w5: v2(2500.45,1109.49) 2500.45,1110.44 2504.42,1114.42 U22.R14@2504.44,1133.28 ; v2(2908.95,339.14) U21.B1@2928.63,358.81
HEXASPI_IO10: TP26.1 U21.A2 U22.M12 | length 1267
  Top Layer w5: v2(2551.67,1212.01) 2551.67,1201.02 2537.17,1186.52 2537.17,1177.17 2534.66,1174.66 2534.66,1174.5 2526.17,1166 2526.01,1166 2523.92,1163.92 2514.56,1163.92 2504.15,1153.5 2504.15,1143.99 2475.91,1115.75 2475.91,1104.09 2492.76,1087.24 TP26.1@2492.76,1045.91 2492.76,1040.91 2478.72,1026.86 2478.72,772.49 2520,731.2 2520,625 2845.23,299.77 v2(2948.32,299.77)
  Bottom Layer w5: v2(2551.67,1212.01) U22.M12@2567.43,1227.77 ; v2(2948.32,299.77) U21.A2@2968,319.44
HEXASPI_IO11: TP27.1 U21.A4 U22.P6 | length 1272.5
  Top Layer w5: v2(2772.12,1149.01) 2772.12,1140.88 2789.12,1123.88 2789.12,1111.51 2798.36,1102.27 2819.31,1102.27 2828.38,1093.2 2828.38,1092.81 2851.76,1069.42 TP27.1@2851.76,1043.91 2859.98,1035.68 2859.98,989.9 ; 2859.99,989.89 2859.99,984.26 2876.28,967.98 2876.28,893.73 2882.6,887.41 2922.78,887.41 2922.88,887.5 2937.38,887.5 2937.48,887.41 2939.59,887.41 2985.57,841.42 2985.57,834.34 2982.15,830.92 2982.15,823.84 2989.22,816.77 2996.3,816.77 2999.72,820.19 3006.8,820.19 3241.65,585.34 3241.65,402.64 3158.9,319.89 3086.54,319.89 v2(3066.42,299.77)
  Bottom Layer w5: U22.P6@2756.39,1164.75 v2(2772.12,1149.01) ; U21.A4@3046.74,319.44 v2(3066.42,299.77)
HEXASPI_IO12: TP28.1 U21.A5 U22.N6 | length 1264.1
  Top Layer w5: v2(2772.12,1180.51) 2789.12,1163.51 2789.12,1143 2797.61,1134.51 2809.47,1134.51 2820,1123.99 2820,1114.99 2820.5,1114.49 2820.5,1113.99 2828.99,1105.5 2836.91,1105.5 2874.99,1067.42 2874.99,988.01 2900,963 2900,912.91 2905,907.91 TP28.1@2917.76,907.91 2918.39,907.27 2942.72,907.27 3257.9,592.09 3257.9,390.9 3166.77,299.77 v2(3105.79,299.77)
  Bottom Layer w5: U22.N6@2756.39,1196.25 v2(2772.12,1180.51) ; U21.A5@3086.11,319.44 v2(3105.79,299.77)
HEXASPI_IO13: TP29.1 U21.B4 U22.R7 | length 1271
  Top Layer w5: v2(2731.3,1103.69) 2735.24,1103.69 2753.03,1085.91 2769.09,1085.91 2803.76,1051.24 TP29.1@2803.76,1045.91 2803.76,1042.91 2811.76,1034.91 2811.76,1018.9 2829.98,1000.67 2829.98,977.45 ; 2829.99,977.44 2829.99,971.83 2831.28,970.53 2831.28,863.72 2860,835 2901.1,835 3003.6,732.5 3050.06,732.5 3208.8,573.75 3208.8,442.15 3138.36,371.7 3131.28,371.7 3088.3,414.72 3081.21,414.72 3072.79,406.3 3072.79,399.22 3102,370.01
  Top Layer w5.22: v2(3066.42,339.14) 3080.14,339.14 3102,360.99 3102,370.01
  Bottom Layer w5: U22.R7@2724.9,1133.27 2724.9,1110.09 v2(2731.3,1103.69) ; U21.B4@3046.74,358.81 v2(3066.42,339.14)
HEXASPI_IO14: TP30.1 U21.B5 U22.N7 | length 1273.5
  Top Layer w5: v2(2740.63,1180.51) 2740.63,1119.38 2757.1,1102.91 2773.31,1102.91 2805.96,1070.25 2821.89,1070.25 2828.72,1063.42 2828.72,1023.94 2844.98,1007.68 2844.98,983.67 ; 2844.99,983.67 2844.99,978.05 2855.76,967.27 TP30.1@2855.76,944.91 2855.76,883.75 2851,879 2851,865.22 2866.22,850 2907.32,850 2922.98,834.34 2930.06,834.34 2942.32,846.59 2949.4,846.59 2955.47,840.52 2955.47,831.44 2944.21,820.18 2944.21,813.1 3009.82,747.5 3056.28,747.5 3223.8,579.98 3223.8,529.69 3223.98,529.51 3223.98,428.98 3142.98,347.98
  Top Layer w5.22: v2(3105.79,339.14) 3134.14,339.14 3142.98,347.98
  Bottom Layer w5: U22.N7@2724.9,1196.25 v2(2740.63,1180.51) ; U21.B5@3086.11,358.81 v2(3105.79,339.14)
HEXASPI_IO15: TP31.1 U21.C5 U22.P8 | length 1273.8
  Top Layer w5: v2(2795.86,991.09) 2795.86,990.35 2811.76,974.45 TP31.1@2811.76,889.91 2811.76,868.11 2812.1,867.77 2812.1,859.9 2871,801 2913.88,801 2927.04,787.84 2927.04,780.75 2912,765.72 2912,755.85 2919.39,748.47 2926.47,748.47 2942.4,764.4 2950.48,764.4 2958.02,756.85 2958.02,749.77 2940.42,732.17 2940.42,725.09 2948.02,717.5 2957.6,717.5 2968.56,728.45 2977.24,728.45 2988.2,717.5 3043.84,717.5 3193.8,567.53 3193.8,448.36 3175,429.56 3167.94,429.56 3157.55,439.97 3150.49,439.97 3143.4,432.88 3143.4,425.81 3153.79,415.41 3153.79,408.36 3144.03,398.6 3136.3,398.6 3117.03,417.86 v2(3105.79,417.86)
  Bottom Layer w5: U22.P8@2693.4,1164.76 2710,1148.17 2710,1060 2778.91,991.09 v2(2795.86,991.09) ; U21.C5@3086.11,398.19 v2(3105.79,417.86)
HEXASPI_NCS: R115.1 TP12.1 U21.A3 U22.R13 | length 1332.9
  Top Layer w5: v2(2458.79,977.88) 2454.76,973.84 TP12.1@2454.76,945.91 2454.76,775.23 2505,724.99 2505,610 2835,279.99 2967.92,279.99 v2(2987.69,299.77)
  Bottom Layer w4: 2987.69,244.1 v2(2987.69,299.77)
  Bottom Layer w5: v2(2458.79,977.88) 2535.92,1055 U22.R13@2535.94,1133.28 ; R115.1@2987.73,199.99 R115.1@2987.72,205.01 ; R115.1@2987.69,205.03 2987.69,244.1 ; v2(2987.69,299.77) U21.A3@3007.37,319.44
I2C1_I3C_SCL: CN3.7 R29.2 R44.2 R58.2 R129.2 R155.1 SB24.1 SB58.1 U22.E5 | length 14726.5
  Top Layer w4: v2(2805.22,1465.78) 2805.44,1465.78 2819.65,1480 2819.65,1504.65 2825,1510 2877.73,1510
  Top Layer w5: v1(804.12,2155.88) 853.24,2205 1305,2205 v1(1401.22,2301.22) ; R29.2@2597.87,2771.23 v1(2597.87,2805.86) ; 2877.73,1510 2901.66,1510 2916.66,1525 2937.87,1525 2972.87,1560 3056.22,1560 3165,1668.77 3165,1686 3179,1700 3202.29,1700 3202.29,1719.99 3207.3,1725 3310,1725 3480,1895 3905,1895 3908.78,1891.22 v1(3908.78,1890) ; v1(5455,3215) 5470,3230 R58.2@5587.3,3230
  L3_SIG w4: v1(1401.22,2301.22) 1420,2282.43 1420,2190 1395,2165 1395,1200 1360,1165 1360,530 1505,385.01 2019.99,385.01 2235,169.99 3610,169.99 v1(3911.22,471.22) 3940,500 3940,650 3912,678 3912,1886.77 v1(3908.78,1890) ; v1(2597.87,2805.86) 2617,2825 3714.95,2825 3734,2844.05 3734,2847.51 v1(3736.48,2850) 3741.48,2855 4103.02,2855 4304.01,3055.99 4920.8,3055.99 4936.81,3072 5062,3072 5182,3192 5432,3192 v1(5455,3215)
  L3_SIG w5: v1(804.12,2155.88) 858.25,2210 1035,2210 1140,2105 1140,1330 v3(1180,1290)
  Bottom Layer w4: U22.E5@2787.9,1448.24 2805.22,1465.57 v2(2805.22,1465.78)
  Bottom Layer w5: v1(804.12,2155.88) R155.1@804.12,2192.01 ; R129.2@1145.12,1290 v3(1180,1290) ; SB58.1@1455.06,2301.22 v1(1401.22,2301.22) 1401.22,2421.22 1707.01,2727 2467.01,2727 2545.87,2805.86 v1(2597.87,2805.86) ; v1(3736.48,2850) CN3.7@3736.48,3400.25 ; SB24.1@3846.01,471.22 v1(3911.22,471.22)
I2C1_I3C_SDA: CN3.10 R32.2 R45.2 R57.2 R127.2 R153.1 SB27.1 SB59.1 U22.C2 | length 14693.9
  Top Layer w5: v1(854.12,2155.88) 888.24,2190 1390,2190 v1(1400,2200) ; R32.2@2657.87,2768.95 v1(2657.87,2805.12) ; v2(2898.11,1526.95) 2911.15,1540 2931.65,1540 2966.65,1575 3050,1575 3150,1675 3150,1722 3178,1750 3202.28,1750 3202.28,1767.27 3215,1780 3340,1780 3470,1910 3890,1910 v1(3910,1930) ; v1(5455,3150) 5490,3185 R57.2@5587.3,3185
  L3_SIG w4: v1(1400,2200) 1375,2175 1375,1220 1335,1180 1335,535 1498.49,371.52 2008.48,371.52 2222,157.99 3624.98,157.99 3955,488.01 3955,660 3934,681 3934,698 v1(3930.78,701.22) 3930.78,1909.22 v1(3910,1930) ; v1(2657.87,2805.12) 3730.13,2805.12 3762.7,2837.69 v1(3972.7,2837.69) 4102.7,2837.69 4308.99,3043.99 4925.78,3043.99 4941.79,3060 5080,3060 5200,3180 5425,3180 v1(5455,3150)
  L3_SIG w5: v1(854.12,2155.88) 888.25,2190 1025,2190 1125,2090 1125,1295 v3(1180,1240)
  Bottom Layer w4: U22.C2@2882.39,1511.24 v2(2898.11,1526.95)
  Bottom Layer w5: v1(854.12,2155.88) R153.1@854.12,2192.01 ; R127.2@1145.12,1240 v3(1180,1240) ; SB59.1@1454.75,2201.22 1401.22,2201.22 v1(1400,2200) 1365,2235 1365,2420 1693.01,2748 2463.01,2748 2540,2825 2638,2825 v1(2657.87,2805.12) ; SB27.1@3844.43,701.22 v1(3930.78,701.22) ; v1(3972.7,2837.69) CN3.10@3972.7,3400.25
LCD_B0: CN2.21 U22.M5 | length 1727.2
  Top Layer w5: CN2.21@3052.88,2501.22 3052.88,2511.99 v1(3052.87,2560)
  L3_SIG w4: v2(2801.33,1214.33) 2789.62,1226.03 2789.62,1249.31 2803,1262.68 2803,1262.8 2826.2,1286 2841,1286 2852,1297 2852,1311.68 2860.81,1320.5 2875.49,1320.5 2880.62,1325.62 2880.62,1340.42 2892.69,1352.5 2932.5,1352.5 2932.99,1353 2934.12,1353 2942.18,1361.06 2958.04,1361.06 2965,1368.01 2965,1369.02 2965.23,1369.25 2965.23,1401.25 3082,1518.02 3082,1530.01 3162,1610.01 3162,1611.06 3170,1619.06 3170,1813 3135,1848 3135,2126.03 3186,2177.03 3186,2364.93 3164,2386.93 3164,2432.98 3052.87,2544.1 v1(3052.87,2560)
  Bottom Layer w5: U22.M5@2787.9,1227.77 v2(2801.33,1214.33)
LCD_B1: CN2.23 U22.F1 | length 1282.1
  Top Layer w5: v1(3002.87,2450) 3002.87,2484 CN2.23@3002.88,2501.22
  L3_SIG w4: v2(2929.6,1432.47) 2929.6,1439.59 2944,1453.99 2944,1505 2988.01,1549 3004.97,1549 3025.98,1549 3122,1645.01 3122,1791 3087,1826 3087,2147 3135,2195 3135,2317.86 v1(3002.87,2450)
  Bottom Layer w4: U22.F1@2913.89,1416.75 v2(2929.6,1432.47)
LCD_B2: CN2.25 U22.C14 | length 1386
  Top Layer w5: v1(2427,2142.5) 2429.5,2145 2557,2145 2817,2405 2870,2405 2952.88,2487.88 CN2.25@2952.88,2501.22
  L3_SIG w4: v1(2427,2142.5) 2425,2140.5 2425,1747.75 2489,1683.75 2489,1579 2470,1560 v2(2460,1560)
  Bottom Layer w5: v2(2460,1560) 2475,1560 2490,1545 2490,1525.65 U22.C14@2504.44,1511.24
LCD_B3: CN2.27 U22.C15 | length 1363
  Top Layer w5: v1(2400,2145) 2415,2160 2552,2160 2812,2420 2860,2420 2902.87,2462.86 2902.87,2486 CN2.27@2902.88,2501.22
  L3_SIG w4: v1(2400,2145) 2413,2132 2413,1742.77 2474.67,1681.1 2474.67,1619.67 2443.18,1588.18 2443.18,1540.95 v2(2457.18,1526.95)
  Bottom Layer w4: v2(2457.18,1526.95) U22.C15@2472.94,1511.24
LCD_B4: CN2.29 U22.E13 | length 1787.4
  Top Layer w5: v1(2231.56,2210) 2266.56,2175 2546,2175 2806,2435 2825,2435 2852.87,2462.86 2852.87,2482 CN2.29@2852.88,2501.22
  L3_SIG w4: v1(2231.56,2210) 2231.56,1571.45 2297.01,1506 2398,1506 2433,1471 2513.14,1471 v2(2520.17,1463.97)
  Bottom Layer w4: v2(2520.17,1463.97) 2529.07,1455.07 ; 2529.09,1455.07 U22.E13@2535.94,1448.24
LCD_B5: CN2.31 U22.D14 | length 1720.9
  Top Layer w5: v1(2230,2240) 2280,2190 2540,2190 2802.87,2452.87 2802.87,2490 CN2.31@2802.88,2501.22
  L3_SIG w4: v1(2230,2240) 2250,2220 2250.02,2150.56 2250.02,1569.99 2256,1564 2301,1519 2406.45,1519 v2(2430,1495.45)
  Bottom Layer w4: v2@2434.65,1495.45 2488.67,1495.45 2494.06,1490.07 U22.D14@2504.44,1479.74
  Bottom Layer w5: v2(2430,1495.45) v2@2434.65,1495.45
LCD_B6: CN2.33 U22.F12 | length 1841.5
  Top Layer w5: v1(2231,2269) 2295,2205 2534,2205 2752.87,2423.87 2752.87,2489 CN2.33@2752.88,2501.22
  L3_SIG w4: v1(2231,2269) 2210,2248 2210,1576.03 2293.03,1493 2394,1493 2428,1459 2501,1459 2510,1450 2514.34,1450 ; 2514.37,1449.97 2530,1449.97 v2(2550,1429.97)
  Bottom Layer w4: v2(2550,1429.97) 2563.22,1416.75 U22.F12@2567.43,1416.75
LCD_B7: CN2.35 U22.P1 | length 3074.7
  Top Layer w5: CN2.35@2702.88,2501.22 2702.88,2512.99 2702.87,2557.86 v1(2705,2560)
  L3_SIG w4: v1(2705,2560) 2798,2653 3507,2653 3600,2560 3600,1850 3598.5,1848.5 3598.5,1433.5 3470.01,1305 3470.01,1235 3385,1150 3226,1150 3158,1082 3108,1082 3060.01,1130 2972,1130 v2(2960,1118)
  Bottom Layer w4: U22.P1@2913.86,1164.75 2960,1118.61 v2(2960,1118)
LCD_BL_CTRL: CN2.43 U22.G4 | length 2147.7
  Top Layer w5: CN2.43@2502.88,2501.22 2502.88,2474 2502.87,2452.12 2555,2400 v1(2600,2400)
  L3_SIG w4: v1(2600,2400) 2650,2400 2742.5,2492.5 2767.5,2492.5 2884.13,2609.12 2965.87,2609.12 2985,2590 2985,2511 3147,2349 3147,2190.02 3099,2142.02 3099,1833 3134,1798 3134,1634 3037,1537 3011,1537 2989,1515 2989,1478.99 2943.6,1433.59 2943.6,1426.67 2931.93,1415 2849.13,1415 v2(2835.11,1400.98)
  Bottom Layer w4: U22.G4@2819.4,1385.25 v2(2835.11,1400.98)
LCD_CLK: CN2.32 U22.G5 | length 1894.3
  Top Layer w5: v1(2802.87,2590) 2802.87,2636 CN2.32@2802.88,2646.31
  L3_SIG w4: v1(2802.87,2590) 2850.87,2638 2997,2638 3030,2605 3030,2550 3152,2428 3152,2381.95 3174,2359.95 3174,2182.01 3123,2131.01 3123,1843 3158,1808 3158,1624.03 3150,1616.03 3150,1615 3070,1535 3070,1523 2957.38,1410.39 2955.39,1410.39 2920,1375 2825,1375 2806.33,1393.67 2806.33,1399.75 v2(2806,1400.09)
  Bottom Layer w4: U22.G5@2787.9,1385.25 2791.16,1385.25 v2(2806,1400.09)
LCD_DE: CN2.22 U22.M13 | length 3218
  Top Layer w5: v1(2154,2544) 2154,2623.5 2145,2632.5 2145,2818 2166,2839 3036.01,2839 3052.87,2822.14 CN2.22@3052.88,2646.31
  L3_SIG w4: v1(2154,2544) 2154,2539 2051.49,2436.49 2051.49,1293.5 2131,1214 2360.98,1214 2387.98,1241 2439.63,1241 2440.63,1242 2490.19,1242 v2(2520.17,1212.01)
  Bottom Layer w5: v2(2520.17,1212.01) U22.M13@2535.94,1227.77
LCD_G0: CN2.4 U22.H4 | length 1773.2
  Top Layer w5: v1(3485,2565) 3502.88,2582.88 CN2.4@3502.88,2646.31
  L3_SIG w4: v2(3050,1404.9) 3069.91,1404.9 3155,1489.99 3155,1586.03 3174,1605.03 3174,1606.08 3182,1614.08 3182,1818 3147,1853 3147,2121.06 3198,2172.06 3198,2338 3440,2580 3470,2580 v1(3485,2565)
  Bottom Layer w4: U22.H4@2819.4,1353.76 2838.63,1373 2922.87,1373 2945.11,1394.99 2952.41,1394.99
  Bottom Layer w5: 2952.41,1394.99 2963.29,1394.99 2978.3,1410 3044.9,1410 v2(3050,1404.9)
LCD_G1: CN2.6 U22.N5 | length 2076.7
  Top Layer w5: v1(3440,2555) 3452.88,2567.88 CN2.6@3452.88,2646.31
  L3_SIG w4: v2(2803.62,1180.51) 2803.62,1188.61 2821.11,1206.1 2821.11,1249.31 2829.31,1257.5 2837.41,1257.5 2850,1270.09 2850,1280 2859,1289 2889.01,1289 2894,1294 2971.42,1294 3022.42,1345 3023.02,1345 3025.02,1347 3099.01,1347 3127,1319 3247,1319 3453,1525 3453,1696 3390,1759 3390,2088 3461,2159 3461,2418 3425,2454 3425,2540 v1(3440,2555)
  Bottom Layer w4: U22.N5@2787.88,1196.25 v2(2803.62,1180.51)
LCD_G2: CN2.8 U22.M2 | length 2216
  Top Layer w5: v1(3402.87,2597.86) CN2.8@3402.88,2646.31
  L3_SIG w4: v2(2949.29,1163) 2949.29,1162.7 2951,1161 3141.94,1161 3155.94,1175 3376.04,1175 3446.01,1244.97 3446.01,1324.01 3574.5,1452.5 3574.5,1858.45 3576,1859.95 3576,2509 3487.13,2597.86 v1(3402.87,2597.86)
  Bottom Layer w4: U22.M2@2882.37,1227.75 2895.13,1215 2920.21,1215 2949.29,1185.92 v2(2949.29,1163)
LCD_G3: CN2.10 U22.M1 | length 2350.4
  Top Layer w5: v1(3352.87,2587.86) CN2.10@3352.88,2646.31
  L3_SIG w4: v2(3137,1099) 3137,1118 3182,1163 3381.02,1163 3458.01,1239.99 3458.01,1313 3586.5,1441.5 3586.5,1853.48 3588,1854.98 3588,2522 3490,2620 3385,2620 v1(3352.87,2587.86)
  Bottom Layer w4: U22.M1@2913.86,1227.75 2928.67,1227.75 2952.41,1204.01
  Bottom Layer w5: 2952.41,1204.01 3026.43,1130 3106.01,1130 v2(3137,1099)
LCD_G4: CN2.12 U22.N15 | length 3542
  Top Layer w5: v1(2066,2573) 2066,2591 2083,2608 2083,2844 2140,2901 3174,2901 3302.87,2772.12 CN2.12@3302.88,2646.31
  L3_SIG w4: v1(2066,2573) 2066,2506 2015.49,2455.49 2015.49,1277.52 2116.02,1177 2377,1177 2402,1202 2429,1202 2450.48,1180.51 v2(2457.18,1180.51)
  Bottom Layer w4: v2(2457.18,1180.51) U22.N15@2472.94,1196.27
LCD_G5: CN2.14 U22.L12 | length 3549.4
  Top Layer w5: v1(2155,2510) 2114.01,2510 2087.33,2536.67 2087.33,2589.33 2097,2599 2097,2835 2149,2887 3142.99,2887 3252.88,2777.1 CN2.14@3252.88,2646.31
  L3_SIG w4: v1(2155,2510) 2145,2510 2063.49,2428.49 2063.49,1298.49 2135.98,1226 2356,1226 2383,1253 2438,1253 2442.51,1257.5 2537.67,1257.5 v2(2551.67,1243.5)
  Bottom Layer w5: v2(2551.67,1243.5) U22.L12@2567.43,1259.27
LCD_G6: CN2.16 U22.N14 | length 3389.8
  Top Layer w5: v1(2111,2574) 2111,2825 2110,2826 2154,2870 3085,2870 3202.87,2752.12 CN2.16@3202.88,2646.31
  L3_SIG w4: v1(2111,2574) 2085,2548 2085,2508.01 2027.49,2450.5 2027.49,1282.5 2120,1190 2373,1190 2397,1214 2434,1214 2453.48,1194.51 2474.67,1194.51 v2(2488.67,1180.51)
  Bottom Layer w4: v2(2488.67,1180.51) U22.N14@2504.44,1196.27
LCD_G7: CN2.18 U22.M14 | length 3297.1
  Top Layer w5: v1(2110,2545) 2130,2565 2130,2824 2160,2854 3076.01,2854 3152.87,2777.14 3152.87,2653 CN2.18@3152.88,2646.31
  L3_SIG w4: v1(2110,2545) 2110,2515 2039.49,2444.49 2039.49,1287.49 2124.98,1202 2367,1202 2394,1229 2471.69,1229 v2(2488.67,1212.01)
  Bottom Layer w5: v2(2488.67,1212.01) U22.M14@2504.44,1227.77
LCD_HSYNC: CN2.26 U22.C6 | length 1216.5
  Top Layer w5: v1(2952.87,2592.12) CN2.26@2952.88,2646.31
  L3_SIG w4: v2(2772.12,1526.95) 2805,1559.84 2805,1649.9 2877,1721.9 2877,2202 2920,2245 2920,2320 2952.87,2352.88 v1(2952.87,2592.12)
  Bottom Layer w4: U22.C6@2756.38,1511.22 v2(2772.12,1526.95)
LCD_INT: CN2.39 U22.F5 | length 2165.6
  Top Layer w5: v1(2602.87,2440) 2602.87,2486 CN2.39@2602.88,2501.22
  L3_SIG w4: v1(2602.87,2440) 2697.87,2535 2775,2535 2863,2623 2982,2623 3005,2600 3005,2511.98 3162,2354.98 3162,2187 3111,2136 3111,1838 3146,1803 3146,1629.01 3039.98,1523 3014,1523 3001,1510 3001,1474 2955,1428 2955,1424.99 2916.99,1386.98 2828.02,1386.98 2820,1395 2820,1407 2812.02,1414.98 2795.97,1414.98 2781.42,1400.42 v2(2771.58,1400.42)
  Bottom Layer w4: v2(2771.58,1400.42) U22.F5@2787.9,1416.75
LCD_ON/OFF: SB34.2 U22.D11 | length 1671.8
  L3_SIG w4: v2(2583.55,1495.07) 2595,1506.51 2595,1575 2572,1598 2572,2121 2594,2143 2594,2365 2572,2387 2572,2492 2748,2668 2928,2668 2945,2685 v1(2945,2705)
  Bottom Layer w4: v2(2583.55,1495.07) 2589.81,1488.81 U22.D11@2598.93,1479.74
  Bottom Layer w5: v1(2945,2705) 2945,2785 2963.62,2803.61 SB34.2@3005,2803.64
